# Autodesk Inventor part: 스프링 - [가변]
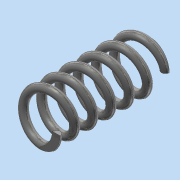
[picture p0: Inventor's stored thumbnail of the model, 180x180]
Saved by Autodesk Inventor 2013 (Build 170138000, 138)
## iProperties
Created: 2015-12
Part Number: 스프링 - [가변]
Material: 강철, 탄소
Document SubType Name: Modeling
Designer: Administrator
Density: 7.87 g/cm^3
Mass: 16.5231 g
Surface Area: 28.4697 cm^2
Volume: 2.0995 cm^3
Author: Administrator
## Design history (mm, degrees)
sketch "스케치1"
  geometry: L1 (0, 0)-(0, 42); L2 (0, 42)-(8, 42); L3 (0, 0)-(8, 0); C1 r 1.5 at (8, 0)
  constraints: 6 end point, 1 centre point, 1 coincident, 1 parallel, 1 perpendicular, 1 vertical
  dimensions: "d0" = 42 distance of L1.start L1.end (derived); "d1" = 8 distance of L1.end L2.end; "d2" = 8 distance of L1.start L3.end; "d3" = 3 diameter of C1
feature "코일1" sketch "스케치1" pitch "d4" = 10; turns "d6" = 6; dims "d5" = 42 (= d0), "d7" = 0, angle "d8" = 90 deg, angle "d9" = 90 deg, "d10" = 0, "d11" = 0
sketch "스케치2"
  geometry: L1 (0, 10)-(42, 10); L2 (42, 10)-(42, -10); L3 (42, -10)-(0, -10); L4 (0, -10)-(0, 10); 2 further points
  constraints: 8 end point, 2 parallel, 1 coincident, 1 horizontal, 1 midpoint, 1 perpendicular
  dimensions: "d12" = 42 distance of L2.end L3.end (derived); "d14" = 20 distance of L1.end L2.end
extrude "돌출1" sketch "스케치2" stored distance "d15" = 10; taper "d16" = 0 deg
node "솔리드1"
